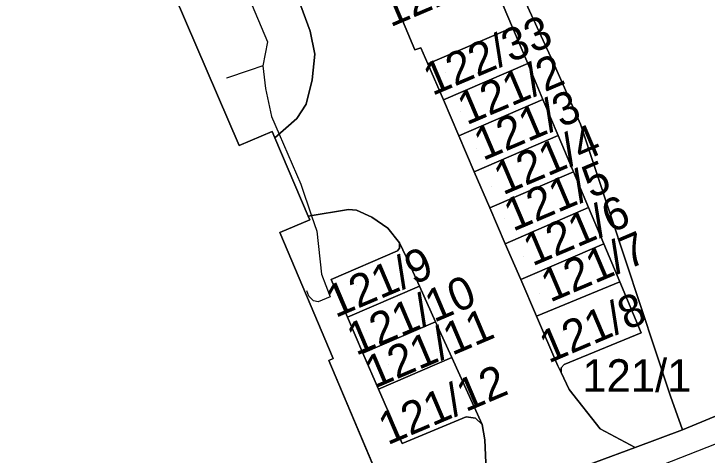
# Model space of a CAD drawing. Extents: x -264070 to -262271, y -1238894 to -1238141.
# Drawn here: x -263210.33 to -263167.78, y -1238789.37 to -1238762.3 of the extents above; entities that cross this region are included whole.
import ezdxf

# ---------------------------------------------------------------- set-up
doc = ezdxf.new("R2010")
doc.units = 0
for name, color, linetype in [('body_kn', 7, 'Continuous'), ('kladpar_druhypozemkov', 7, 'Continuous'), ('kladpar_hranice', 7, 'Continuous'), ('kladpar_parcelnecisla', 7, 'Continuous'), ('kladpar_plochy', 7, 'Continuous'), ('tarchy_linie', 7, 'Continuous'), ('zappar_hrandruhpozemk', 7, 'Continuous')]:
    doc.layers.add(name, color=color, linetype=linetype)

msp = doc.modelspace()

# ---------------------------------------------------------------- linework, layer by layer
at = {"layer": 'body_kn'}
for p, q in [((-263192.14, -1238763.36), (-263192.14, -1238763.36)), ((-263179.73, -1238763.13), (-263179.73, -1238763.13)), ((-263179.73, -1238763.13), (-263179.73, -1238763.13)), ((-263194.77, -1238764.01), (-263194.77, -1238764.01)), ((-263185.71, -1238764.5), (-263185.71, -1238764.5)), ((-263185.34, -1238764.38), (-263185.34, -1238764.38)), ((-263191.85, -1238764.76), (-263191.85, -1238764.76)), ((-263195.05, -1238765.49), (-263195.05, -1238765.49)), ((-263195.05, -1238765.49), (-263195.05, -1238765.49)), ((-263184.91, -1238765.37), (-263184.91, -1238765.37)), ((-263178.79, -1238765.34), (-263178.79, -1238765.34)), ((-263178.79, -1238765.34), (-263178.79, -1238765.34)), ((-263177.15, -1238765.45), (-263177.15, -1238765.45)), ((-263195.88, -1238765.77), (-263195.88, -1238765.77)), ((-263197.28, -1238766.25), (-263197.28, -1238766.25)), ((-263192.01, -1238766.34), (-263192.01, -1238766.34)), ((-263194.88, -1238766.87), (-263194.88, -1238766.87)), ((-263183.96, -1238767.58), (-263183.96, -1238767.58)), ((-263177.86, -1238767.55), (-263177.86, -1238767.55)), ((-263177.86, -1238767.55), (-263177.86, -1238767.55)), ((-263192.38, -1238767.83), (-263192.38, -1238767.83)), ((-263194.51, -1238768.59), (-263194.51, -1238768.59)), ((-263192.96, -1238768.71), (-263192.96, -1238768.71)), ((-263175.56, -1238769.06), (-263175.56, -1238769.06)), ((-263194.48, -1238769.51), (-263194.48, -1238769.51)), ((-263194.05, -1238769.67), (-263194.05, -1238769.67)), ((-263183.01, -1238769.78), (-263183.01, -1238769.78)), ((-263176.92, -1238769.76), (-263176.92, -1238769.76)), ((-263176.92, -1238769.76), (-263176.92, -1238769.76)), ((-263194.32, -1238769.91), (-263194.32, -1238769.91)), ((-263196.49, -1238770.37), (-263196.49, -1238770.37)), ((-263196.49, -1238770.37), (-263196.49, -1238770.37)), ((-263182.07, -1238771.99), (-263182.07, -1238771.99)), ((-263175.99, -1238771.98), (-263175.99, -1238771.98)), ((-263175.99, -1238771.98), (-263175.99, -1238771.98)), ((-263192.72, -1238772.75), (-263192.72, -1238772.75)), ((-263189.78, -1238774.3), (-263189.78, -1238774.3)), ((-263189.29, -1238774.35), (-263189.29, -1238774.35)), ((-263181.12, -1238774.19), (-263181.12, -1238774.19)), ((-263175.06, -1238774.18), (-263175.06, -1238774.18)), ((-263175.06, -1238774.18), (-263175.06, -1238774.18)), ((-263192.27, -1238774.71), (-263192.27, -1238774.71)), ((-263192.17, -1238774.93), (-263192.17, -1238774.93)), ((-263192.06, -1238774.68), (-263192.06, -1238774.68)), ((-263188.35, -1238774.77), (-263188.35, -1238774.77)), ((-263194, -1238775.71), (-263194, -1238775.71)), ((-263191.74, -1238775.63), (-263191.74, -1238775.63)), ((-263187.38, -1238775.45), (-263187.38, -1238775.45)), ((-263186.65, -1238776.34), (-263186.65, -1238776.34)), ((-263180.17, -1238776.4), (-263180.17, -1238776.4)), ((-263174.12, -1238776.4), (-263174.12, -1238776.4)), ((-263174.12, -1238776.4), (-263174.12, -1238776.4)), ((-263186.79, -1238776.83), (-263186.79, -1238776.83)), ((-263186.66, -1238776.67), (-263186.66, -1238776.67)), ((-263186.25, -1238777.21), (-263186.25, -1238777.21)), ((-263191.44, -1238778.27), (-263191.44, -1238778.27)), ((-263190.85, -1238778.59), (-263190.85, -1238778.59)), ((-263190.85, -1238778.59), (-263190.85, -1238778.59)), ((-263179.22, -1238778.6), (-263179.22, -1238778.6)), ((-263173.13, -1238778.74), (-263173.13, -1238778.74)), ((-263173.13, -1238778.74), (-263173.13, -1238778.74)), ((-263185.43, -1238779.01), (-263185.43, -1238779.01)), ((-263192.34, -1238779.29), (-263192.34, -1238779.29)), ((-263192.22, -1238779.63), (-263192.22, -1238779.63)), ((-263191.94, -1238779.91), (-263191.94, -1238779.91)), ((-263191.66, -1238779.96), (-263191.66, -1238779.96)), ((-263190.92, -1238779.67), (-263190.92, -1238779.67)), ((-263178.25, -1238780.85), (-263178.25, -1238780.85)), ((-263189.85, -1238780.91), (-263189.85, -1238780.91)), ((-263184.44, -1238781.2), (-263184.44, -1238781.2)), ((-263171.82, -1238781.86), (-263171.82, -1238781.86)), ((-263171.82, -1238781.86), (-263171.82, -1238781.86)), ((-263190.72, -1238783.44), (-263190.72, -1238783.44)), ((-263188.9, -1238783.11), (-263188.9, -1238783.11)), ((-263188.9, -1238783.11), (-263188.9, -1238783.11)), ((-263183.45, -1238783.38), (-263183.45, -1238783.38)), ((-263191, -1238783.56), (-263191, -1238783.56)), ((-263176.56, -1238783.82), (-263176.56, -1238783.82)), ((-263176.95, -1238783.9), (-263176.95, -1238783.9)), ((-263176.74, -1238784.3), (-263176.74, -1238784.3)), ((-263176.73, -1238784.01), (-263176.73, -1238784.01)), ((-263187.95, -1238785.32), (-263187.95, -1238785.32)), ((-263187.95, -1238785.32), (-263187.95, -1238785.32)), ((-263176.24, -1238785.35), (-263176.24, -1238785.35)), ((-263170.02, -1238785.75), (-263170.02, -1238785.75)), ((-263182.57, -1238787.03), (-263182.57, -1238787.03)), ((-263181.99, -1238787.1), (-263181.99, -1238787.1)), ((-263181.59, -1238787.5), (-263181.59, -1238787.5)), ((-263174.35, -1238787.77), (-263174.35, -1238787.77)), ((-263169.28, -1238787.82), (-263169.28, -1238787.82)), ((-263169.28, -1238787.82), (-263169.28, -1238787.82)), ((-263181.43, -1238788.43), (-263181.43, -1238788.43)), ((-263186.5, -1238788.67), (-263186.5, -1238788.67)), ((-263186.5, -1238788.67), (-263186.5, -1238788.67)), ((-263172.2, -1238788.9), (-263172.2, -1238788.9))]:
    msp.add_line(p, q, dxfattribs=at)
at = {"layer": 'kladpar_druhypozemkov'}
for p, q in [((-263183.86, -1238765.92), (-263183.86, -1238765.92)), ((-263182.91, -1238768.26), (-263182.91, -1238768.26)), ((-263181.95, -1238770.53), (-263181.95, -1238770.53)), ((-263181.03, -1238772.86), (-263181.03, -1238772.86)), ((-263180.21, -1238774.85), (-263180.21, -1238774.85)), ((-263179.04, -1238777.19), (-263179.04, -1238777.19)), ((-263189.28, -1238778.98), (-263189.28, -1238778.98)), ((-263178.09, -1238779.43), (-263178.09, -1238779.43)), ((-263188.69, -1238781.71), (-263188.69, -1238781.71)), ((-263176.65, -1238781.79), (-263176.65, -1238781.79)), ((-263187.35, -1238783.8), (-263187.35, -1238783.8)), ((-263172.95, -1238784.36), (-263172.95, -1238784.36)), ((-263184.93, -1238786.59), (-263184.93, -1238786.59))]:
    msp.add_line(p, q, dxfattribs=at)
at = {"layer": 'kladpar_hranice'}
for points in [[(-263175.8, -1238721.68), (-263174.69, -1238722.04), (-263172.18, -1238728.04), (-263172.18, -1238728.37), (-263172.3, -1238728.79), (-263175.24, -1238730.13), (-263157.74, -1238769.49), (-263140.82, -1238762.6), (-263136.45, -1238774.22), (-263169.28, -1238787.82), (-263170.02, -1238785.75), (-263175.56, -1238769.06), (-263177.15, -1238765.45), (-263197.91, -1238720.28), (-263193.95, -1238718.58), (-263190.79, -1238725.87), (-263179.51, -1238720.86), (-263178.59, -1238722.87), (-263175.8, -1238721.68)], [(-263197.91, -1238720.28), (-263177.15, -1238765.45), (-263175.56, -1238769.06), (-263170.02, -1238785.75), (-263169.28, -1238787.82)], [(-263196.49, -1238770.37), (-263201.12, -1238759.62), (-263201.45, -1238756.12), (-263200.29, -1238756.03), (-263200.32, -1238755.55), (-263203.08, -1238755.77), (-263203.1, -1238755.46), (-263199.99, -1238755.23), (-263198.42, -1238755.18), (-263197.14, -1238755.46), (-263195.91, -1238756.01), (-263194.95, -1238757.09), (-263193.37, -1238760.01), (-263192.14, -1238763.36), (-263191.85, -1238764.76), (-263192.01, -1238766.34), (-263192.38, -1238767.83), (-263192.96, -1238768.71), (-263194.32, -1238769.91), (-263194.48, -1238769.51), (-263196.49, -1238770.37)], [(-263179.73, -1238763.13), (-263184.91, -1238765.37), (-263185.34, -1238764.38), (-263185.71, -1238764.5), (-263187.5, -1238760.24), (-263187.15, -1238760.11), (-263181.95, -1238757.86), (-263179.73, -1238763.13)], [(-263169.28, -1238787.82), (-263172.2, -1238788.9), (-263174.35, -1238787.77), (-263176.24, -1238785.35), (-263176.74, -1238784.3), (-263176.73, -1238784.01), (-263176.56, -1238783.82), (-263171.82, -1238781.86), (-263173.13, -1238778.74), (-263174.12, -1238776.4), (-263175.06, -1238774.18), (-263175.99, -1238771.98), (-263176.92, -1238769.76), (-263177.86, -1238767.55), (-263178.79, -1238765.34), (-263179.73, -1238763.13), (-263181.95, -1238757.86)], [(-263201.12, -1238759.62), (-263196.49, -1238770.37), (-263194.48, -1238769.51), (-263194.32, -1238769.91), (-263192.27, -1238774.71), (-263192.17, -1238774.93), (-263194, -1238775.71), (-263190.72, -1238783.44), (-263191, -1238783.56), (-263187, -1238792.99), (-263225.74, -1238809.65), (-263240.99, -1238773.98)], [(-263181.36, -1238789.85), (-263181.43, -1238788.43), (-263181.59, -1238787.5), (-263183.45, -1238783.38), (-263184.44, -1238781.2), (-263185.43, -1238779.01), (-263186.25, -1238777.21), (-263186.65, -1238776.34), (-263187.38, -1238775.45), (-263188.35, -1238774.77), (-263189.29, -1238774.35), (-263189.78, -1238774.3), (-263192.27, -1238774.71), (-263194.32, -1238769.91), (-263192.96, -1238768.71), (-263192.38, -1238767.83), (-263192.01, -1238766.34), (-263191.85, -1238764.76), (-263192.14, -1238763.36), (-263193.37, -1238760.01)], [(-263187.5, -1238760.24), (-263185.71, -1238764.5), (-263185.34, -1238764.38), (-263184.91, -1238765.37), (-263183.96, -1238767.58), (-263183.01, -1238769.78), (-263182.07, -1238771.99), (-263181.12, -1238774.19), (-263180.17, -1238776.4), (-263179.22, -1238778.6), (-263178.25, -1238780.85), (-263176.95, -1238783.9), (-263176.74, -1238784.3), (-263176.24, -1238785.35), (-263174.35, -1238787.77), (-263172.2, -1238788.9), (-263181.94, -1238792.5)], [(-263178.79, -1238765.34), (-263183.96, -1238767.58), (-263184.91, -1238765.37), (-263179.73, -1238763.13), (-263178.79, -1238765.34)], [(-263177.86, -1238767.55), (-263183.01, -1238769.78), (-263183.96, -1238767.58), (-263178.79, -1238765.34), (-263177.86, -1238767.55)], [(-263176.92, -1238769.76), (-263182.07, -1238771.99), (-263183.01, -1238769.78), (-263177.86, -1238767.55), (-263176.92, -1238769.76)], [(-263169.28, -1238787.82), (-263136.45, -1238774.22), (-263129.74, -1238771.43), (-263119.79, -1238767.71)], [(-263175.99, -1238771.98), (-263181.12, -1238774.19), (-263182.07, -1238771.99), (-263176.92, -1238769.76), (-263175.99, -1238771.98)], [(-263175.06, -1238774.18), (-263180.17, -1238776.4), (-263181.12, -1238774.19), (-263175.99, -1238771.98), (-263175.06, -1238774.18)], [(-263187, -1238792.99), (-263191, -1238783.56), (-263190.72, -1238783.44), (-263194, -1238775.71), (-263192.17, -1238774.93), (-263192.27, -1238774.71), (-263189.78, -1238774.3), (-263189.29, -1238774.35), (-263188.35, -1238774.77), (-263187.38, -1238775.45), (-263186.65, -1238776.34), (-263186.66, -1238776.67), (-263186.79, -1238776.83), (-263190.85, -1238778.59), (-263189.85, -1238780.91), (-263188.9, -1238783.11), (-263187.95, -1238785.32), (-263186.5, -1238788.67), (-263182.57, -1238787.03), (-263181.99, -1238787.1), (-263181.59, -1238787.5), (-263181.43, -1238788.43), (-263181.36, -1238789.85)], [(-263174.12, -1238776.4), (-263179.22, -1238778.6), (-263180.17, -1238776.4), (-263175.06, -1238774.18), (-263174.12, -1238776.4)], [(-263190.85, -1238778.59), (-263186.79, -1238776.83), (-263186.66, -1238776.67), (-263186.65, -1238776.34), (-263186.25, -1238777.21), (-263185.43, -1238779.01), (-263189.85, -1238780.91), (-263190.85, -1238778.59)], [(-263173.13, -1238778.74), (-263178.25, -1238780.85), (-263179.22, -1238778.6), (-263174.12, -1238776.4), (-263173.13, -1238778.74)], [(-263171.82, -1238781.86), (-263176.56, -1238783.82), (-263176.73, -1238784.01), (-263176.74, -1238784.3), (-263176.95, -1238783.9), (-263178.25, -1238780.85), (-263173.13, -1238778.74), (-263171.82, -1238781.86)], [(-263188.9, -1238783.11), (-263189.85, -1238780.91), (-263185.43, -1238779.01), (-263184.44, -1238781.2), (-263188.9, -1238783.11)], [(-263187.95, -1238785.32), (-263188.9, -1238783.11), (-263184.44, -1238781.2), (-263183.45, -1238783.38), (-263187.95, -1238785.32)], [(-263186.5, -1238788.67), (-263187.95, -1238785.32), (-263183.45, -1238783.38), (-263181.59, -1238787.5), (-263181.99, -1238787.1), (-263182.57, -1238787.03), (-263186.5, -1238788.67)], [(-263239.49, -1238816.11), (-263232.66, -1238813.33), (-263231.55, -1238812.88), (-263228.25, -1238811.54), (-263212.56, -1238804.3), (-263207.04, -1238801.79), (-263181.94, -1238792.5), (-263172.2, -1238788.9), (-263169.28, -1238787.82)]]:
    msp.add_lwpolyline(points, dxfattribs=at)
at = {"layer": 'kladpar_plochy'}
for p, q in [((-263192.27, -1238774.71), (-263189.78, -1238774.3)), ((-263189.78, -1238774.3), (-263189.29, -1238774.35)), ((-263189.29, -1238774.35), (-263188.35, -1238774.77)), ((-263194, -1238775.71), (-263192.17, -1238774.93)), ((-263192.17, -1238774.93), (-263192.27, -1238774.71)), ((-263188.35, -1238774.77), (-263187.38, -1238775.45)), ((-263190.72, -1238783.44), (-263194, -1238775.71)), ((-263187.38, -1238775.45), (-263186.65, -1238776.34)), ((-263186.65, -1238776.34), (-263186.66, -1238776.67)), ((-263186.79, -1238776.83), (-263190.85, -1238778.59)), ((-263186.66, -1238776.67), (-263186.79, -1238776.83)), ((-263190.85, -1238778.59), (-263189.85, -1238780.91)), ((-263189.85, -1238780.91), (-263188.9, -1238783.11)), ((-263191, -1238783.56), (-263190.72, -1238783.44)), ((-263188.9, -1238783.11), (-263187.95, -1238785.32)), ((-263187, -1238792.99), (-263191, -1238783.56)), ((-263187.95, -1238785.32), (-263186.5, -1238788.67)), ((-263186.5, -1238788.67), (-263182.57, -1238787.03)), ((-263182.57, -1238787.03), (-263181.99, -1238787.1)), ((-263181.99, -1238787.1), (-263181.59, -1238787.5)), ((-263181.59, -1238787.5), (-263181.43, -1238788.43)), ((-263181.43, -1238788.43), (-263181.36, -1238789.85))]:
    msp.add_line(p, q, dxfattribs=at)
for points in [[(-263175.8, -1238721.68), (-263174.69, -1238722.04), (-263172.18, -1238728.04), (-263172.18, -1238728.37), (-263172.3, -1238728.79), (-263175.24, -1238730.13), (-263157.74, -1238769.49), (-263140.82, -1238762.6), (-263136.45, -1238774.22), (-263169.28, -1238787.82), (-263170.02, -1238785.75), (-263175.56, -1238769.06), (-263177.15, -1238765.45), (-263197.91, -1238720.28), (-263193.95, -1238718.58), (-263190.79, -1238725.87), (-263179.51, -1238720.86), (-263178.59, -1238722.87)], [(-263196.49, -1238770.37), (-263201.12, -1238759.62), (-263201.45, -1238756.12), (-263200.29, -1238756.03), (-263200.32, -1238755.55), (-263203.08, -1238755.77), (-263203.1, -1238755.46), (-263199.99, -1238755.23), (-263198.42, -1238755.18), (-263197.14, -1238755.46), (-263195.91, -1238756.01), (-263194.95, -1238757.09), (-263193.37, -1238760.01), (-263192.14, -1238763.36), (-263191.85, -1238764.76), (-263192.01, -1238766.34), (-263192.38, -1238767.83), (-263192.96, -1238768.71), (-263194.32, -1238769.91), (-263194.48, -1238769.51)], [(-263179.73, -1238763.13), (-263184.91, -1238765.37), (-263185.34, -1238764.38), (-263185.71, -1238764.5), (-263187.5, -1238760.24), (-263187.15, -1238760.11), (-263181.95, -1238757.86)], [(-263178.79, -1238765.34), (-263183.96, -1238767.58), (-263184.91, -1238765.37), (-263179.73, -1238763.13)], [(-263177.86, -1238767.55), (-263183.01, -1238769.78), (-263183.96, -1238767.58), (-263178.79, -1238765.34)], [(-263176.92, -1238769.76), (-263182.07, -1238771.99), (-263183.01, -1238769.78), (-263177.86, -1238767.55)], [(-263175.99, -1238771.98), (-263181.12, -1238774.19), (-263182.07, -1238771.99), (-263176.92, -1238769.76)], [(-263175.06, -1238774.18), (-263180.17, -1238776.4), (-263181.12, -1238774.19), (-263175.99, -1238771.98)], [(-263174.12, -1238776.4), (-263179.22, -1238778.6), (-263180.17, -1238776.4), (-263175.06, -1238774.18)], [(-263190.85, -1238778.59), (-263186.79, -1238776.83), (-263186.66, -1238776.67), (-263186.65, -1238776.34), (-263186.25, -1238777.21), (-263185.43, -1238779.01), (-263189.85, -1238780.91)], [(-263173.13, -1238778.74), (-263178.25, -1238780.85), (-263179.22, -1238778.6), (-263174.12, -1238776.4)], [(-263171.82, -1238781.86), (-263176.56, -1238783.82), (-263176.73, -1238784.01), (-263176.74, -1238784.3), (-263176.95, -1238783.9), (-263178.25, -1238780.85), (-263173.13, -1238778.74)], [(-263188.9, -1238783.11), (-263189.85, -1238780.91), (-263185.43, -1238779.01), (-263184.44, -1238781.2)], [(-263187.95, -1238785.32), (-263188.9, -1238783.11), (-263184.44, -1238781.2), (-263183.45, -1238783.38)], [(-263186.5, -1238788.67), (-263187.95, -1238785.32), (-263183.45, -1238783.38), (-263181.59, -1238787.5), (-263181.99, -1238787.1), (-263182.57, -1238787.03)]]:
    msp.add_lwpolyline(points, close=True, dxfattribs=at)
for points in [[(-263197.91, -1238720.28), (-263177.15, -1238765.45), (-263175.56, -1238769.06), (-263170.02, -1238785.75), (-263169.28, -1238787.82), (-263172.2, -1238788.9), (-263174.35, -1238787.77), (-263176.24, -1238785.35), (-263176.74, -1238784.3), (-263176.73, -1238784.01), (-263176.56, -1238783.82), (-263171.82, -1238781.86), (-263173.13, -1238778.74), (-263174.12, -1238776.4), (-263175.06, -1238774.18), (-263175.99, -1238771.98), (-263176.92, -1238769.76), (-263177.86, -1238767.55), (-263178.79, -1238765.34), (-263179.73, -1238763.13), (-263181.95, -1238757.86)], [(-263201.12, -1238759.62), (-263196.49, -1238770.37), (-263194.48, -1238769.51), (-263194.32, -1238769.91), (-263192.27, -1238774.71), (-263192.17, -1238774.93), (-263194, -1238775.71), (-263190.72, -1238783.44), (-263191, -1238783.56), (-263187, -1238792.99), (-263225.74, -1238809.65), (-263240.99, -1238773.98)], [(-263181.36, -1238789.85), (-263181.43, -1238788.43), (-263181.59, -1238787.5), (-263183.45, -1238783.38), (-263184.44, -1238781.2), (-263185.43, -1238779.01), (-263186.25, -1238777.21), (-263186.65, -1238776.34), (-263187.38, -1238775.45), (-263188.35, -1238774.77), (-263189.29, -1238774.35), (-263189.78, -1238774.3), (-263192.27, -1238774.71), (-263194.32, -1238769.91), (-263192.96, -1238768.71), (-263192.38, -1238767.83), (-263192.01, -1238766.34), (-263191.85, -1238764.76), (-263192.14, -1238763.36), (-263193.37, -1238760.01)], [(-263187.5, -1238760.24), (-263185.71, -1238764.5), (-263185.34, -1238764.38), (-263184.91, -1238765.37), (-263183.96, -1238767.58), (-263183.01, -1238769.78), (-263182.07, -1238771.99), (-263181.12, -1238774.19), (-263180.17, -1238776.4), (-263179.22, -1238778.6), (-263178.25, -1238780.85), (-263176.95, -1238783.9), (-263176.74, -1238784.3), (-263176.24, -1238785.35), (-263174.35, -1238787.77), (-263172.2, -1238788.9), (-263181.94, -1238792.5)], [(-263239.49, -1238816.11), (-263232.66, -1238813.33), (-263231.55, -1238812.88), (-263228.25, -1238811.54), (-263212.56, -1238804.3), (-263207.04, -1238801.79), (-263181.94, -1238792.5), (-263172.2, -1238788.9), (-263169.28, -1238787.82), (-263136.45, -1238774.22), (-263129.74, -1238771.43), (-263119.79, -1238767.71)]]:
    msp.add_lwpolyline(points, dxfattribs=at)
at = {"layer": 'tarchy_linie'}
for points in [[(-263216.74, -1238718.14), (-263216.04, -1238719.08), (-263214.32, -1238721.38), (-263212.05, -1238724.55), (-263210.29, -1238727.79), (-263208.04, -1238732.7), (-263207.63, -1238733.79), (-263206.08, -1238737.92), (-263204.92, -1238740.51), (-263201.43, -1238748.28), (-263200.99, -1238749.25), (-263198.49, -1238755.18), (-263194.77, -1238764.01), (-263195.05, -1238765.49), (-263195.88, -1238765.77), (-263197.28, -1238766.25)], [(-263195.05, -1238765.49), (-263194.88, -1238766.87), (-263194.51, -1238768.59), (-263194.05, -1238769.67), (-263192.72, -1238772.75), (-263192.06, -1238774.68), (-263191.74, -1238775.63), (-263191.44, -1238778.27), (-263190.92, -1238779.67), (-263191.66, -1238779.96), (-263191.94, -1238779.91), (-263192.22, -1238779.63), (-263192.34, -1238779.29)]]:
    msp.add_lwpolyline(points, dxfattribs=at)
at = {"layer": 'zappar_hrandruhpozemk'}
msp.add_line((-263125.02, -1238772.07), (-263175.41, -1238791.89), dxfattribs=at)

# ---------------------------------------------------------------- texts
at = {"layer": 'kladpar_parcelnecisla'}
for s, p in [('122/2', (-263187.22, -1238763.13)), ('122/33', (-263184.645, -1238767.343)), ('121/2', (-263182.543, -1238769.146)), ('121/3', (-263181.537, -1238771.333)), ('121/4', (-263180.313, -1238773.443)), ('121/5', (-263179.694, -1238775.674)), ('121/6', (-263178.503, -1238777.803)), ('121/7', (-263177.42, -1238780.024)), ('121/9', (-263190.593, -1238780.973)), ('121/10', (-263189.332, -1238783.292)), ('121/8', (-263177.515, -1238783.762)), ('121/11', (-263188.226, -1238785.319)), ('121/12', (-263187.393, -1238788.783))]:
    msp.add_text(s, height=2, rotation=23, dxfattribs=at).set_placement(p)
msp.add_text('121/1', height=2, dxfattribs=at).set_placement((-263175.437, -1238785.49))

doc.saveas('drawing.dxf')
